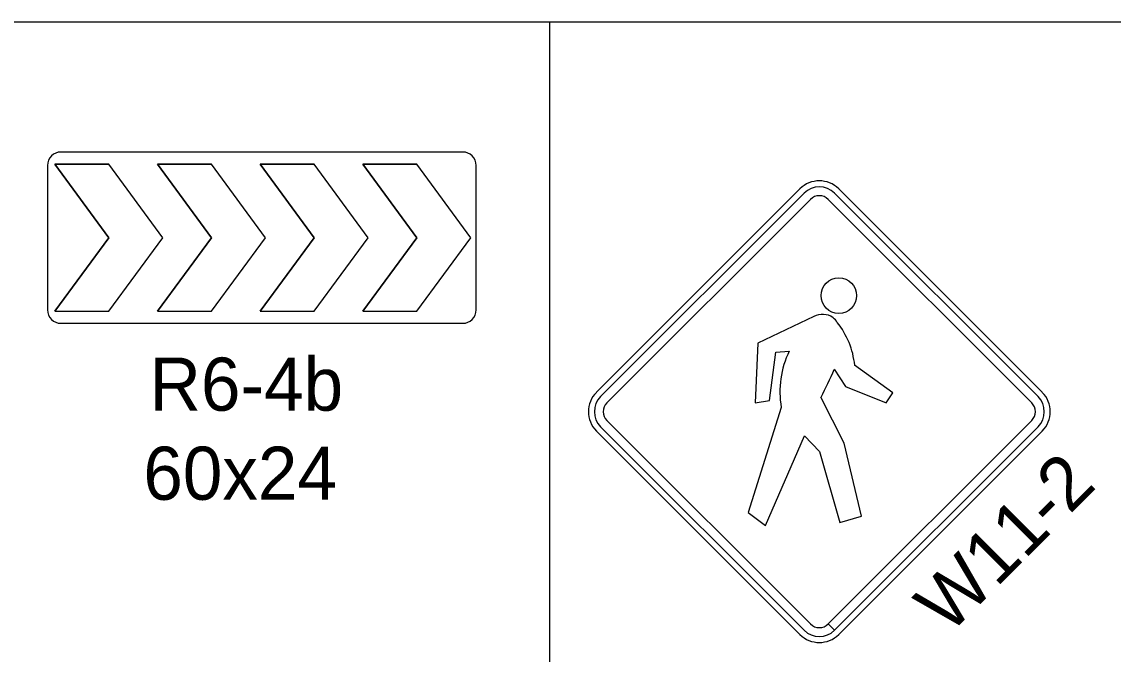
# Model space of a CAD drawing. Extents: x 1458 to 4498, y 17709 to 24109.
# Drawn here: x 2633.6 to 2939.3, y 21279.6 to 21456.8 of the extents above; entities that cross this region are included whole.
import ezdxf

# ---------------------------------------------------------------- set-up
doc = ezdxf.new("R2010")
doc.units = 0
for name, color, linetype in [('GSOUTLINE', 7, 'Continuous'), ('P_ODOT_PLAN_TBlock', 7, 'Continuous'), ('P_TRAF_SIGN_SignDetails', 7, 'Continuous'), ('P_TRAF_TCP_General', 7, 'Continuous')]:
    doc.layers.add(name, color=color, linetype=linetype)

msp = doc.modelspace()

# ---------------------------------------------------------------- linework, layer by layer
at = {"layer": 'GSOUTLINE'}
for p, q in [((2757.1, 21420.34), (2644.6, 21420.34)), ((2640.85, 21416.59), (2640.85, 21376.09)), ((2642.85, 21416.97), (2657.97, 21416.97)), ((2657.97, 21396.34), (2642.85, 21416.97)), ((2657.97, 21416.97), (2642.85, 21416.97)), ((2642.85, 21416.97), (2657.97, 21396.34)), ((2673.09, 21396.34), (2657.97, 21416.97)), ((2673.09, 21396.34), (2657.97, 21416.97)), ((2671.6, 21416.97), (2686.72, 21416.97)), ((2686.72, 21396.34), (2671.6, 21416.97)), ((2686.72, 21416.97), (2671.6, 21416.97)), ((2671.6, 21416.97), (2686.72, 21396.34)), ((2701.84, 21396.34), (2686.72, 21416.97)), ((2701.84, 21396.34), (2686.72, 21416.97)), ((2700.35, 21416.97), (2715.47, 21416.97)), ((2715.47, 21396.34), (2700.35, 21416.97)), ((2715.47, 21416.97), (2700.35, 21416.97)), ((2700.35, 21416.97), (2715.47, 21396.34)), ((2730.59, 21396.34), (2715.47, 21416.97)), ((2730.59, 21396.34), (2715.47, 21416.97)), ((2729.1, 21416.97), (2744.22, 21416.97)), ((2744.22, 21396.34), (2729.1, 21416.97)), ((2744.22, 21416.97), (2729.1, 21416.97)), ((2729.1, 21416.97), (2744.22, 21396.34)), ((2759.34, 21396.34), (2744.22, 21416.97)), ((2759.34, 21396.34), (2744.22, 21416.97)), ((2760.85, 21376.09), (2760.85, 21416.59)), ((2642.85, 21375.72), (2657.97, 21396.34)), ((2657.97, 21396.34), (2642.85, 21375.72)), ((2657.97, 21375.72), (2673.09, 21396.34)), ((2657.97, 21375.72), (2673.09, 21396.34)), ((2671.6, 21375.72), (2686.72, 21396.34)), ((2686.72, 21396.34), (2671.6, 21375.72)), ((2686.72, 21375.72), (2701.84, 21396.34)), ((2686.72, 21375.72), (2701.84, 21396.34)), ((2700.35, 21375.72), (2715.47, 21396.34)), ((2715.47, 21396.34), (2700.35, 21375.72)), ((2715.47, 21375.72), (2730.59, 21396.34)), ((2715.47, 21375.72), (2730.59, 21396.34)), ((2729.1, 21375.72), (2744.22, 21396.34)), ((2744.22, 21396.34), (2729.1, 21375.72)), ((2744.22, 21375.72), (2759.34, 21396.34)), ((2744.22, 21375.72), (2759.34, 21396.34)), ((2642.85, 21375.72), (2657.97, 21375.72)), ((2642.85, 21375.72), (2657.97, 21375.72)), ((2671.6, 21375.72), (2686.72, 21375.72)), ((2671.6, 21375.72), (2686.72, 21375.72)), ((2700.35, 21375.72), (2715.47, 21375.72)), ((2700.35, 21375.72), (2715.47, 21375.72)), ((2729.1, 21375.72), (2744.22, 21375.72)), ((2729.1, 21375.72), (2744.22, 21375.72)), ((2644.6, 21372.34), (2757.1, 21372.34))]:
    msp.add_line(p, q, dxfattribs=at)
for centre, start, end in [((2644.6, 21416.59), 90, 180), ((2757.1, 21416.59), 0, 90), ((2644.6, 21376.09), 180, 270), ((2757.1, 21376.09), 270, 0)]:
    msp.add_arc(centre, 3.75, start, end, dxfattribs=at)
at = {"layer": 'P_ODOT_PLAN_TBlock'}
for p, q in [((2488.57, 21456.82), (3132.73, 21456.82)), ((2781.52, 21129.65), (2781.52, 21456.82))]:
    msp.add_line(p, q, dxfattribs=at)
at = {"layer": 'P_TRAF_SIGN_SignDetails'}
for p, q in [((2855.44, 21374.22), (2839.79, 21366.76)), ((2855.44, 21374.22), (2839.79, 21366.76)), ((2855.44, 21374.21), (2855.44, 21374.22)), ((2855.44, 21374.21), (2855.44, 21374.22)), ((2855.44, 21374.21), (2855.44, 21374.22)), ((2855.44, 21374.21), (2855.44, 21374.22)), ((2839.79, 21366.76), (2839, 21350.02)), ((2839.79, 21366.76), (2839, 21350.02)), ((2843, 21350.72), (2844.76, 21364.26)), ((2843, 21350.72), (2844.76, 21364.26)), ((2844.76, 21364.26), (2848.53, 21364.54)), ((2844.76, 21364.26), (2848.53, 21364.54)), ((2877.57, 21352.91), (2866.86, 21360.62)), ((2877.57, 21352.91), (2866.86, 21360.62)), ((2861.11, 21359.45), (2864.26, 21354.64)), ((2861.11, 21359.45), (2864.26, 21354.64)), ((2864.26, 21354.64), (2875.69, 21350.07)), ((2864.26, 21354.64), (2875.69, 21350.07)), ((2863.88, 21338.73), (2857.43, 21351.66)), ((2863.88, 21338.73), (2857.43, 21351.66)), ((2875.69, 21350.07), (2877.57, 21352.91)), ((2875.69, 21350.07), (2877.57, 21352.91)), ((2846.3, 21348.77), (2837.07, 21319.35)), ((2846.3, 21348.77), (2837.07, 21319.35)), ((2839, 21350.02), (2843, 21350.72)), ((2839, 21350.02), (2843, 21350.72)), ((2841.91, 21315.65), (2852.82, 21340.82)), ((2841.91, 21315.65), (2852.82, 21340.82)), ((2852.82, 21340.82), (2856.98, 21336.41)), ((2852.82, 21340.82), (2856.98, 21336.41)), ((2868.8, 21318.3), (2863.88, 21338.73)), ((2868.8, 21318.3), (2863.88, 21338.73)), ((2856.98, 21336.41), (2862.74, 21316.54)), ((2856.98, 21336.41), (2862.74, 21316.54)), ((2837.07, 21319.35), (2841.91, 21315.65)), ((2837.07, 21319.35), (2841.91, 21315.65)), ((2862.74, 21316.54), (2868.8, 21318.3)), ((2862.74, 21316.54), (2868.8, 21318.3))]:
    msp.add_line(p, q, dxfattribs=at)
msp.add_circle((2862.43, 21380.11), 4.99, dxfattribs=at)
msp.add_circle((2862.43, 21380.11), 4.99, dxfattribs=at)
for centre, radius, start, end in [((2857.91, 21369.82), 5.04, 54.5243, 119.3215), ((2857.91, 21369.82), 5.04, 54.5243, 119.3215), ((2855.23, 21367.92), 8.21, 34.4955, 46.9601), ((2855.23, 21367.92), 8.21, 34.4955, 46.9601), ((2844.02, 21358.27), 22.97, 5.8484, 38.5024), ((2844.02, 21358.27), 22.97, 5.8484, 38.5024), ((2871.66, 21353.23), 25.74, 153.9401, 190.0139), ((2871.66, 21353.23), 25.74, 153.9401, 190.0139), ((2795.03, 21385.85), 71.16, 331.2887, 338.2182), ((2795.03, 21385.85), 71.16, 331.2887, 338.2182)]:
    msp.add_arc(centre, radius, start, end, dxfattribs=at)
at = {"layer": 'P_TRAF_TCP_General'}
for p, q in [((2851.54, 21410.01), (2794.53, 21353.01)), ((2919.39, 21353.01), (2862.39, 21410.01)), ((2852.72, 21408.83), (2795.71, 21351.83)), ((2797.48, 21350.06), (2854.49, 21407.06)), ((2859.43, 21407.06), (2916.44, 21350.06)), ((2859.43, 21407.06), (2916.44, 21350.06)), ((2918.21, 21351.83), (2861.2, 21408.83)), ((2854.49, 21288.1), (2797.48, 21345.11)), ((2916.44, 21345.11), (2859.45, 21288.12)), ((2794.53, 21342.16), (2851.54, 21285.15)), ((2795.71, 21343.34), (2852.72, 21286.34)), ((2861.22, 21286.36), (2918.21, 21343.34)), ((2862.39, 21285.15), (2919.39, 21342.16)), ((2861.2, 21286.34), (2859.43, 21288.1)), ((2861.2, 21286.34), (2859.43, 21288.1)), ((2859.45, 21288.12), (2861.22, 21286.36)), ((2859.45, 21288.12), (2861.22, 21286.36))]:
    msp.add_line(p, q, dxfattribs=at)
for centre, radius, start, end in [((2856.96, 21404.59), 7.67, 45, 135), ((2856.96, 21404.59), 6, 45, 135), ((2856.96, 21404.59), 3.5, 45, 135), ((2799.96, 21347.58), 7.67, 135, 225), ((2799.96, 21347.58), 6, 135, 225), ((2799.96, 21347.58), 6, 135, 225), ((2913.97, 21347.58), 6, 315, 45), ((2913.97, 21347.58), 7.67, 315, 45), ((2799.96, 21347.58), 3.5, 135, 225), ((2913.97, 21347.58), 3.5, 315, 45), ((2856.96, 21290.58), 3.5, 225, 315), ((2856.96, 21290.58), 7.67, 225, 315), ((2856.96, 21290.58), 6, 225, 315)]:
    msp.add_arc(centre, radius, start, end, dxfattribs=at)

# ---------------------------------------------------------------- texts
for s, p in [('R6-4b', (2669.42, 21347.86)), ('60x24', (2667.66, 21322.9))]:
    msp.add_text(s, height=14.88, dxfattribs=at).set_placement(p)
msp.add_text('W11-2', height=14.994, rotation=45, dxfattribs=at).set_placement((2893.22, 21284.79))

doc.saveas('drawing.dxf')
